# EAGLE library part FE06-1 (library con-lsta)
FEMALE HEADER
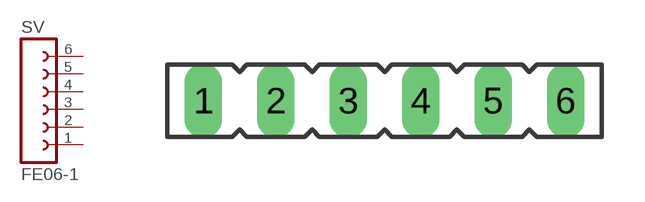
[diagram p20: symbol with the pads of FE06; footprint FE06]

Designator prefix SV

## FE06-1 (OC_FARNELL: unknown; OC_NEWARK: unknown)  [FE06]
1  1  pas
2  2  pas
3  3  pas
4  4  pas
5  5  pas
6  6  pas

## Footprint FE06 (pad centres in mm)
FEMALE HEADER
drill 0.813 long: 1 -6.35,0; 2 -3.81,0; 3 -1.27,0; 4 1.27,0; 5 3.81,0; 6 6.35,0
